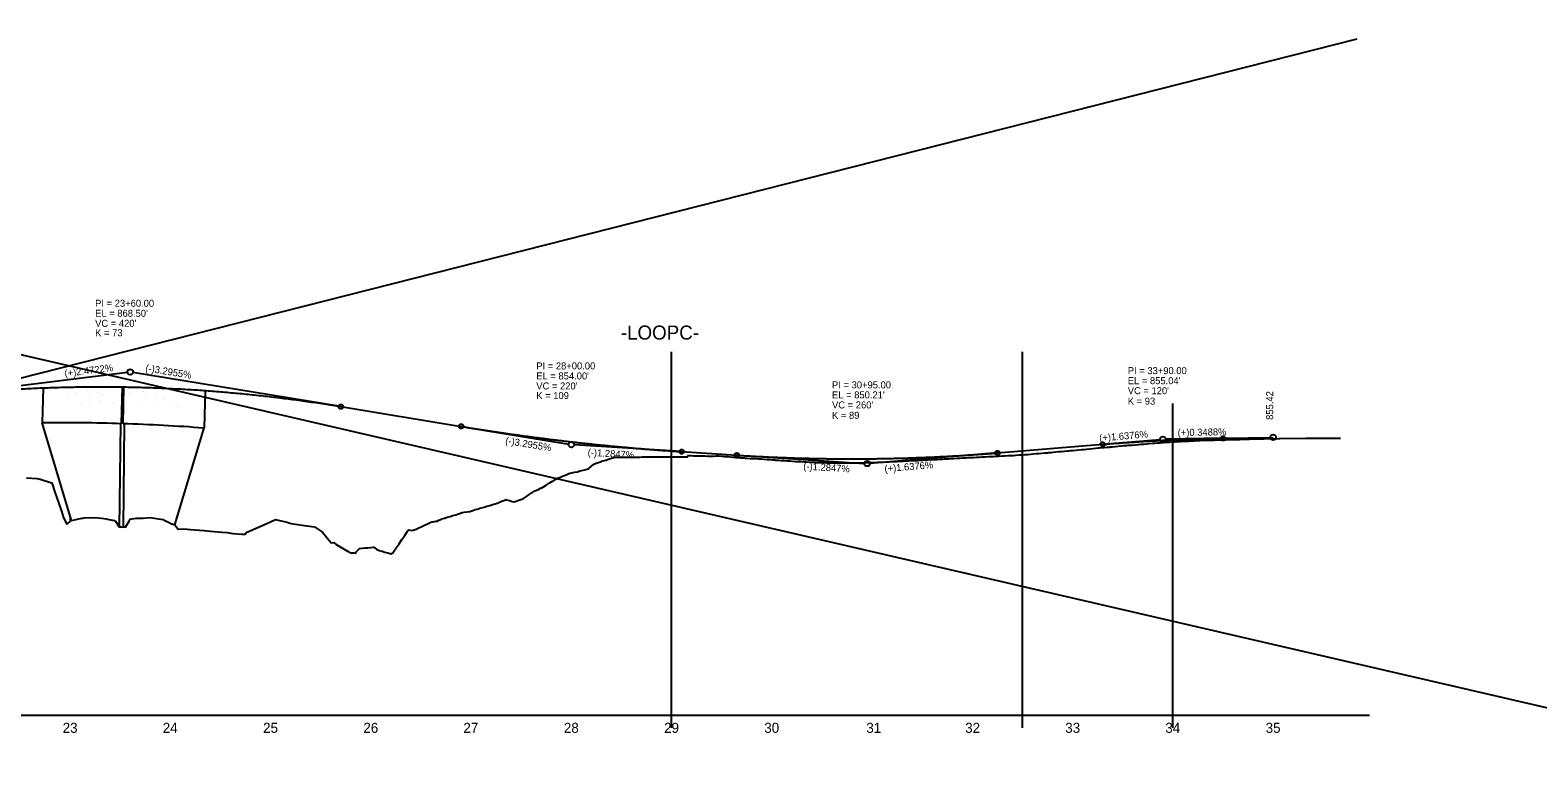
# Model space of a CAD drawing. Extents: x 570622 to 580296, y -55533 to -48575.
# Drawn here: x 575281 to 576785, y -51546 to -50801 of the extents above; entities that cross this region are included whole.
import ezdxf

# ---------------------------------------------------------------- set-up
doc = ezdxf.new("R2010")
doc.units = 0
for name, color, linetype in [('Default', 7, 'Continuous'), ('Exist Profile Cell', 7, 'Continuous'), ('Exist Vertical Profile Ground Line', 7, 'Continuous'), ('Exist Vertical Profile Horizontal Axis Label Major', 7, 'Continuous'), ('Prop Vertical Profile Curve Label', 7, 'Continuous'), ('Prop Vertical Profile Grade', 7, 'Continuous'), ('Prop Vertical Profile Grade Label', 7, 'Continuous'), ('Prop VPI Label', 7, 'Continuous')]:
    doc.layers.add(name, color=color, linetype=linetype)

msp = doc.modelspace()

# ---------------------------------------------------------------- linework, layer by layer
at = {"layer": 'Default'}
for p, q in [((575921, -51497.2), (575921, -51122)), ((576271, -51497.2), (576271, -51122)), ((575294.2, -51158.1), (575293, -51192.8)), ((575372.4, -51193.7), (575373.3, -51157.2)), ((575373.8, -51193.8), (575374.7, -51157.2)), ((575318.1, -51164.1), (575318.1, -51164.1)), ((575319.5, -51165.7), (575319.5, -51165.7)), ((575319.5, -51165.7), (575319.5, -51165.7)), ((575326.2, -51162.4), (575326.2, -51162.4)), ((575327.7, -51164), (575327.7, -51164)), ((575327.7, -51164), (575327.7, -51164)), ((575331.3, -51174.5), (575331.3, -51174.5)), ((575331.3, -51174.5), (575331.3, -51174.5)), ((575337.9, -51162.1), (575337.9, -51162.1)), ((575339.4, -51163.7), (575339.4, -51163.7)), ((575339.5, -51163.7), (575339.5, -51163.7)), ((575339.7, -51172.3), (575339.7, -51172.3)), ((575339.7, -51172.3), (575339.7, -51172.3)), ((575349.6, -51163.2), (575349.6, -51163.2)), ((575351.1, -51164.8), (575351.1, -51164.8)), ((575351.1, -51164.8), (575351.1, -51164.8)), ((575351.3, -51171.9), (575351.3, -51171.9)), ((575351.5, -51171.9), (575351.5, -51171.9)), ((575352.3, -51164), (575352.3, -51164)), ((575353.8, -51165.6), (575353.8, -51165.6)), ((575353.8, -51165.6), (575353.8, -51165.6)), ((575363, -51173), (575363, -51173)), ((575363, -51173), (575363, -51173)), ((575365.7, -51173.7), (575365.7, -51173.7)), ((575365.7, -51173.7), (575365.7, -51173.7)), ((575380, -51162.5), (575380, -51162.5)), ((575381.5, -51164.1), (575381.5, -51164.1)), ((575381.5, -51164.1), (575381.5, -51164.1)), ((575393.3, -51161.8), (575393.3, -51161.8)), ((575393.3, -51172.6), (575393.3, -51172.6)), ((575393.3, -51172.6), (575393.3, -51172.6)), ((575394.1, -51162.2), (575394.1, -51162.2)), ((575395.1, -51163.4), (575395.1, -51163.4)), ((575406.6, -51163.8), (575406.6, -51163.8)), ((575406.7, -51171.9), (575406.7, -51171.9)), ((575407, -51171.9), (575407, -51171.9)), ((575408.1, -51165.5), (575408.1, -51165.5)), ((575408.1, -51165.5), (575408.1, -51165.5)), ((575414.3, -51168.3), (575414.3, -51168.3)), ((575416.3, -51169.9), (575416.3, -51169.9)), ((575416.3, -51169.9), (575416.3, -51169.9)), ((575420, -51173.8), (575420, -51173.8)), ((575420, -51173.8), (575420, -51173.8)), ((575455.8, -51160.8), (575454.6, -51198.1)), ((576421, -51497.2), (576421, -51173.7)), ((575428.5, -51178), (575428.5, -51178)), ((575428.5, -51178), (575428.5, -51178)), ((575322.3, -51290.3), (575293, -51192.8)), ((575370.4, -51297.3), (575371.5, -51193.8)), ((575374.2, -51297.4), (575375.3, -51193.8)), ((575425.6, -51294.6), (575454.6, -51198.1)), ((576268.6, -51221), (576268.6, -51221)), ((575321.3, -51290.3), (575321.3, -51287)), ((575322.3, -51290.3), (575321.3, -51290.3))]:
    msp.add_line(p, q, dxfattribs=at)
for start, end in [(88.1608, 90.5075), (85.7299, 88.1202)]:
    msp.add_arc((575310.2, -53131.3), 1938.5, start, end, dxfattribs=at)
at = {"layer": 'Exist Profile Cell'}
for p, q in [((576604.4, -50810.1), (573705.9, -51546.1)), ((573874.3, -50801.3), (576976.7, -51519.5)), ((574021, -51484.7), (576617.2, -51484.7))]:
    msp.add_line(p, q, dxfattribs=at)
at = {"layer": 'Exist Vertical Profile Ground Line'}
for points in [[(576264.1, -51225.3), (576264.7, -51225.2), (576267.6, -51225), (576270.4, -51224.9), (576273.2, -51224.7), (576276.2, -51224.5), (576278.8, -51224.2), (576281.7, -51224), (576284.5, -51223.7), (576287.3, -51223.5), (576290.1, -51223.3), (576293, -51223), (576295.8, -51222.8), (576296.7, -51222.7), (576298.6, -51222.5), (576299.5, -51222.4), (576301.4, -51222.3), (576304.3, -51222), (576307.1, -51221.7), (576309.9, -51221.4), (576312.7, -51221.2), (576315.6, -51220.9), (576316.7, -51220.8), (576318.4, -51220.7), (576320, -51220.6), (576321.2, -51220.5), (576324, -51220.2), (576326.9, -51219.9), (576329.7, -51219.7), (576332.5, -51219.4), (576334.7, -51219.2), (576335.3, -51219.1), (576338.1, -51218.8), (576341, -51218.5), (576343.8, -51218.3), (576346.6, -51218), (576347.4, -51217.9), (576349.4, -51217.7), (576352.3, -51217.5), (576355.1, -51217.3), (576357.9, -51217.1), (576358.5, -51217), (576360.7, -51216.8), (576363.6, -51216.5), (576366.4, -51216.3), (576369.2, -51216), (576369.7, -51215.9), (576372, -51215.7), (576374.9, -51215.5), (576376.4, -51215.4), (576377.7, -51215.3), (576379.1, -51215.2), (576380.5, -51215.1), (576383.3, -51214.8), (576386.2, -51214.6), (576386.9, -51214.6), (576389, -51214.4), (576391.8, -51214.2), (576394.6, -51213.9), (576397.4, -51213.7), (576400.5, -51213.4), (576403.1, -51213.2), (576405.9, -51213), (576408.7, -51212.8), (576411.6, -51212.6), (576414.4, -51212.4), (576417.2, -51212.2), (576417.7, -51212.1), (576420, -51212), (576421.1, -51211.9), (576422.9, -51211.8), (576425.7, -51211.7), (576428.5, -51211.5), (576431.3, -51211.4), (576434.2, -51211.2), (576437, -51211.1), (576439.8, -51210.9), (576442.6, -51210.8), (576444.9, -51210.7), (576445.5, -51210.6), (576448.3, -51210.5), (576450.4, -51210.4), (576451.1, -51210.3), (576454.1, -51210.3), (576456.7, -51210.2), (576459.6, -51210.1), (576462.4, -51210.1), (576465.2, -51210), (576468, -51209.9), (576470.9, -51209.9), (576472.2, -51209.8), (576473.7, -51209.8), (576476.5, -51209.7), (576479.3, -51209.7), (576482.2, -51209.6), (576485, -51209.5), (576487.8, -51209.5), (576490.6, -51209.4), (576493.5, -51209.3), (576495.9, -51209.3), (576496.3, -51209.3)], [(576496.3, -51209.3), (576496.8, -51209.3), (576497.4, -51209.2), (576526.8, -51208.7), (576527.5, -51208.6), (576553.5, -51208.1), (576554.5, -51208.1), (576583.6, -51208.4), (576588, -51208.4)], [(575810.1, -51247), (575812.9, -51245.9), (575815.7, -51244.7), (575818.6, -51243.6), (575819.3, -51243.2), (575821.4, -51242.9), (575824.2, -51242.3), (575827, -51241.7), (575829.9, -51241), (575832.7, -51240.3), (575835.5, -51239.6), (575837.6, -51239), (575838.3, -51238.4), (575841.2, -51236.1), (575843.3, -51234.3), (575844, -51234), (575846.8, -51233), (575849, -51232.2), (575849.6, -51232), (575852.5, -51231), (575854, -51230.5), (575855.3, -51230.1), (575858.1, -51229.2), (575860.9, -51228.3), (575863.7, -51227.4), (575864.3, -51227.3), (575866.6, -51227.2), (575869.4, -51227.2), (575872.2, -51227.1), (575874.3, -51227.1), (575875, -51227.1), (575877.9, -51227.2), (575878.3, -51227.2), (575880.7, -51227.1), (575883.5, -51227.1), (575886.3, -51227.1), (575889.2, -51227.1), (575892, -51227), (575894.8, -51227), (575897.6, -51227), (575900.5, -51226.9), (575903.3, -51226.9), (575904.2, -51226.9), (575906.1, -51226.9), (575908.9, -51226.9), (575911.8, -51226.9), (575914.6, -51227), (575916.7, -51227), (575917.4, -51227), (575920.2, -51227), (575923, -51227), (575925.9, -51227), (575927.2, -51227), (575928.7, -51227), (575931.5, -51227), (575934.3, -51227), (575936.8, -51227), (575937.2, -51225.6), (575940, -51225.7), (575942.8, -51225.8), (575945.6, -51225.8), (575948.5, -51225.9), (575951.3, -51226), (575954.1, -51226), (575956.9, -51226.1), (575959.8, -51226.1), (575960.9, -51226.2), (575961.4, -51226.1), (575962.6, -51226.2), (575965.4, -51226), (575967.1, -51225.8), (575968.2, -51225.9), (575971.1, -51226.2), (575973.4, -51226.4), (575973.9, -51226.5), (575976.7, -51226.7), (575979.5, -51226.9), (575982.3, -51227.1), (575985.2, -51227.4), (575988, -51227.6), (575990.1, -51227.8), (575990.8, -51227.8), (575993.6, -51228), (575994.1, -51228.1), (575996.5, -51228.2), (575999.3, -51228.4), (576002.1, -51228.5), (576004.9, -51228.7), (576007.8, -51228.9), (576010.6, -51229), (576012.9, -51229.2), (576013.4, -51229.2), (576016.2, -51229.4), (576019.1, -51229.6), (576021.9, -51229.8), (576023.8, -51230), (576024.7, -51230.1), (576027.5, -51230.2), (576030.4, -51230.4), (576032.4, -51230.6), (576033.2, -51230.6)], [(576033.2, -51230.6), (576036, -51230.8), (576038.8, -51231), (576041.6, -51231.2), (576044.5, -51231.4), (576047.6, -51231.6), (576050.1, -51231.7), (576052.9, -51231.8), (576055.8, -51232), (576058.6, -51232.1), (576060.8, -51232.3), (576061.4, -51232.3), (576062.1, -51232.3), (576062.4, -51232.3), (576064.2, -51232.4), (576067.1, -51232.5), (576069.9, -51232.5), (576072.7, -51232.6), (576075.5, -51232.7), (576078.4, -51232.8), (576081.2, -51232.9), (576082.6, -51232.9), (576084, -51232.9), (576086.9, -51232.9), (576089.7, -51232.9), (576092.5, -51232.9), (576095.3, -51232.9), (576098.1, -51232.9), (576100.9, -51232.9), (576103, -51232.9), (576103.8, -51232.9), (576106.6, -51232.8), (576109.4, -51232.7), (576110.2, -51232.7), (576112.2, -51232.7), (576115.1, -51232.6), (576117.9, -51232.5), (576119, -51232.5), (576120.7, -51232.4), (576123.5, -51232.4), (576126.4, -51232.3), (576129.2, -51232.2), (576130.1, -51232.2), (576132, -51232.1), (576134.8, -51231.9), (576137.7, -51231.8), (576140.5, -51231.6), (576142.3, -51231.5), (576143.3, -51231.5), (576146.1, -51231.4), (576149, -51231.2), (576151.8, -51231.1), (576154.6, -51231), (576157.4, -51230.8), (576160.2, -51230.7), (576163.1, -51230.5), (576165.9, -51230.4), (576166.7, -51230.3), (576168.7, -51230.2), (576171.5, -51230.1), (576174.4, -51230), (576176.6, -51229.9), (576177.2, -51229.8), (576180, -51229.7), (576182.8, -51229.5), (576185.7, -51229.4), (576188.5, -51229.2), (576191.3, -51229.1), (576192.5, -51229), (576194.1, -51228.9), (576196.2, -51228.8), (576197, -51228.8), (576199.8, -51228.6), (576202.6, -51228.4), (576205.4, -51228.3), (576208.3, -51228.1), (576211.1, -51227.9), (576213.9, -51227.8), (576214.4, -51227.8), (576216.7, -51227.6), (576217.3, -51227.6), (576219.5, -51227.5), (576220.3, -51227.5), (576222.4, -51227.4), (576225.2, -51227.2), (576228, -51227.1), (576230.8, -51226.9), (576233.7, -51226.8), (576236.5, -51226.7), (576238.2, -51226.6), (576239.3, -51226.5), (576242.1, -51226.4), (576245, -51226.2), (576247.8, -51226.1), (576250.6, -51226), (576253.4, -51225.8), (576256.3, -51225.7), (576259.1, -51225.5), (576260.3, -51225.5), (576261.9, -51225.4), (576264.1, -51225.3)], [(575277.6, -51247.7), (575287.9, -51248.6), (575291, -51249.1), (575301.4, -51252.4), (575302.7, -51252.7), (575303.6, -51254.8), (575305.4, -51261), (575312.5, -51281.1), (575314.4, -51287.7), (575317.8, -51294.2), (575322.3, -51290.3), (575325.4, -51289.8), (575332.7, -51288.1), (575333.7, -51287.9), (575335.5, -51287.8), (575345.5, -51287.5), (575352.2, -51288.1), (575357.1, -51288.6), (575358.2, -51288.9), (575359.8, -51289.4), (575365.2, -51290.5), (575366.1, -51290.8), (575366.4, -51291.2), (575370, -51296.7), (575372.5, -51296.8), (575376.4, -51296.9), (575379.8, -51291.2), (575381, -51289.1), (575382.5, -51288.8), (575387.3, -51288.2), (575394, -51287.9), (575401, -51287.5), (575413.4, -51289.4), (575414.1, -51289.5), (575414.8, -51289.9), (575419.7, -51292.3), (575422.3, -51293.6), (575422.9, -51293.8), (575425.6, -51294.6), (575428.3, -51298.7), (575429.5, -51299.1), (575434.4, -51298.8), (575441.2, -51299.3), (575454.7, -51300.2), (575461, -51301), (575472.5, -51301.9), (575477.6, -51302.5), (575483.3, -51303.4), (575492.3, -51303.9), (575495.7, -51304), (575497.1, -51301.9), (575498.3, -51301.7), (575520.1, -51292.2), (575526, -51289.4), (575528.7, -51290.2), (575537.6, -51291.9), (575540.3, -51293.2), (575541.6, -51293.5), (575543.4, -51293.8), (575557.3, -51295.8), (575564.8, -51296.7)], [(575564.8, -51296.7), (575572.9, -51301.9), (575581.3, -51312.5), (575584.1, -51312.2), (575586.5, -51314.4), (575598.3, -51321.4), (575600.4, -51322.7), (575601.1, -51322.7), (575604, -51322.8), (575605.3, -51322.9), (575606.8, -51321.2), (575609.6, -51318.2), (575612.4, -51318), (575615.3, -51317.8), (575618.1, -51317.6), (575620.9, -51317.4), (575623.7, -51317.1), (575624.1, -51317.1), (575626.5, -51318.9), (575627.8, -51319.8), (575629.4, -51320.2), (575632.2, -51321.1), (575635, -51321.9), (575637.8, -51322.7), (575640.9, -51323.5), (575642.8, -51322.7), (575643.5, -51321.7), (575646.3, -51317.7), (575649.1, -51313.6), (575652, -51309.4), (575654.8, -51305.3), (575657.6, -51301.1), (575658.6, -51299.7), (575660.4, -51299.9), (575662.9, -51300.2), (575663.3, -51300.1), (575666.1, -51298.9), (575668.9, -51297.6), (575671.7, -51296.4), (575674.6, -51295.1), (575677.4, -51293.8), (575680.2, -51292.5), (575681.7, -51291.8), (575683, -51291.6), (575685.8, -51291.1), (575687.2, -51290.9), (575688.7, -51290.2), (575691.5, -51288.9), (575691.9, -51288.6), (575694.3, -51288), (575697.1, -51287.2), (575700, -51286.3), (575702.8, -51285.5), (575705.6, -51284.6), (575708.4, -51283.7), (575711.3, -51282.7), (575712.2, -51282.4), (575714.1, -51282.2), (575716.9, -51281.9), (575719.7, -51281.5), (575722.6, -51280.4), (575725, -51279.5), (575725.4, -51279.4), (575728.2, -51278.6), (575729.6, -51278.2), (575731, -51277.8), (575733.9, -51277), (575736.7, -51276.2), (575739.5, -51275.3), (575742.3, -51274.5), (575745.1, -51273.6), (575748, -51272.7), (575749.2, -51272.2), (575750.8, -51271.6), (575753.6, -51270.5), (575755.9, -51269.5), (575756.4, -51269.7), (575759.3, -51270.5), (575762.1, -51271.3), (575764, -51271.8), (575764.9, -51271.5), (575767.7, -51270.5), (575770.6, -51269.5), (575773.4, -51268.4), (575776.2, -51266.4), (575779, -51264.4), (575781.9, -51262.4), (575782.4, -51262), (575784.7, -51260.9), (575787.5, -51259.7), (575790.3, -51258.3), (575791.4, -51257.8), (575793.2, -51256.8), (575796, -51255), (575798.8, -51253.3), (575801.6, -51251.5), (575804.4, -51249.7), (575805.6, -51249), (575807, -51248.2), (575807.3, -51248.1), (575810.1, -51247)]]:
    msp.add_lwpolyline(points, dxfattribs=at)
at = {"layer": 'Prop Vertical Profile Curve Label'}
for centre in [(575591, -51176.8), (575711, -51196.5), (575931, -51221.7), (576351, -51214.4), (576471, -51208.4), (575986, -51225.3), (576246, -51223)]:
    msp.add_circle(centre, 2.25, dxfattribs=at)
at = {"layer": 'Prop Vertical Profile Grade'}
for p, q in [((575591, -51176.8), (575711, -51196.5)), ((576246, -51223), (576351, -51214.4)), ((576471, -51208.4), (576521, -51207.5)), ((575931, -51221.7), (575986, -51225.3))]:
    msp.add_line(p, q, dxfattribs=at)
for points in [[(575171, -51168.1), (575179.4, -51167.1), (575187.8, -51166.1), (575196.2, -51165.2), (575204.6, -51164.3), (575213, -51163.5), (575221.4, -51162.8), (575229.8, -51162), (575238.2, -51161.4), (575246.6, -51160.7), (575255, -51160.2), (575263.4, -51159.6), (575271.8, -51159.1), (575280.2, -51158.7), (575288.6, -51158.3), (575297, -51158), (575305.4, -51157.7), (575313.8, -51157.5), (575322.2, -51157.3), (575330.6, -51157.1), (575339, -51157), (575347.4, -51157), (575355.8, -51157), (575364.2, -51157), (575372.6, -51157.1), (575381, -51157.3), (575389.4, -51157.5), (575397.8, -51157.7), (575406.2, -51158), (575414.6, -51158.4), (575423, -51158.8), (575431.4, -51159.2), (575439.8, -51159.7), (575448.2, -51160.2), (575456.6, -51160.8), (575465, -51161.4), (575473.4, -51162.1), (575481.8, -51162.9), (575490.2, -51163.6), (575498.6, -51164.5), (575507, -51165.3), (575515.4, -51166.3), (575523.8, -51167.2), (575532.2, -51168.3), (575540.6, -51169.3), (575549, -51170.4), (575557.4, -51171.6), (575565.8, -51172.8), (575574.2, -51174.1), (575582.6, -51175.4), (575591, -51176.8)], [(575711, -51196.5), (575715.4, -51197.2), (575719.8, -51198), (575724.2, -51198.7), (575728.6, -51199.4), (575733, -51200), (575737.4, -51200.7), (575741.8, -51201.4), (575746.2, -51202), (575750.6, -51202.7), (575755, -51203.3), (575759.4, -51204), (575763.8, -51204.6), (575768.2, -51205.2), (575772.6, -51205.8), (575777, -51206.4), (575781.4, -51207), (575785.8, -51207.6), (575790.2, -51208.1), (575794.6, -51208.7), (575799, -51209.3), (575803.4, -51209.8), (575807.8, -51210.3), (575812.2, -51210.9), (575816.6, -51211.4), (575821, -51211.9), (575825.4, -51212.4), (575829.8, -51212.9), (575834.2, -51213.4), (575838.6, -51213.8), (575843, -51214.3), (575847.4, -51214.8), (575851.8, -51215.2), (575856.2, -51215.6), (575860.6, -51216.1), (575865, -51216.5), (575869.4, -51216.9), (575873.8, -51217.3), (575878.2, -51217.7), (575882.6, -51218.1), (575887, -51218.5), (575891.4, -51218.8), (575895.8, -51219.2), (575900.2, -51219.5), (575904.6, -51219.9), (575909, -51220.2), (575913.4, -51220.5), (575917.8, -51220.8), (575922.2, -51221.1), (575926.6, -51221.4), (575931, -51221.7)], [(576351, -51214.4), (576353.4, -51214.2), (576355.8, -51214), (576358.2, -51213.8), (576360.6, -51213.6), (576363, -51213.4), (576365.4, -51213.2), (576367.8, -51213.1), (576370.2, -51212.9), (576372.6, -51212.7), (576375, -51212.6), (576377.4, -51212.4), (576379.8, -51212.2), (576382.2, -51212.1), (576384.6, -51211.9), (576387, -51211.8), (576389.4, -51211.6), (576391.8, -51211.5), (576394.2, -51211.3), (576396.6, -51211.2), (576399, -51211), (576401.4, -51210.9), (576403.8, -51210.8), (576406.2, -51210.7), (576408.6, -51210.5), (576411, -51210.4), (576413.4, -51210.3), (576415.8, -51210.2), (576418.2, -51210.1), (576420.6, -51210), (576423, -51209.9), (576425.4, -51209.8), (576427.8, -51209.7), (576430.2, -51209.6), (576432.6, -51209.5), (576435, -51209.4), (576437.4, -51209.3), (576439.8, -51209.2), (576442.2, -51209.1), (576444.6, -51209), (576447, -51209), (576449.4, -51208.9), (576451.8, -51208.8), (576454.2, -51208.8), (576456.6, -51208.7), (576459, -51208.6), (576461.4, -51208.6), (576463.8, -51208.5), (576466.2, -51208.5), (576468.6, -51208.4), (576471, -51208.4)], [(575986, -51225.3), (575991.2, -51225.6), (575996.4, -51225.9), (576001.6, -51226.2), (576006.8, -51226.5), (576012, -51226.7), (576017.2, -51227), (576022.4, -51227.2), (576027.6, -51227.4), (576032.8, -51227.6), (576038, -51227.8), (576043.2, -51228), (576048.4, -51228.2), (576053.6, -51228.3), (576058.8, -51228.4), (576064, -51228.6), (576069.2, -51228.7), (576074.4, -51228.7), (576079.6, -51228.8), (576084.8, -51228.9), (576090, -51228.9), (576095.2, -51228.9), (576100.4, -51228.9), (576105.6, -51228.9), (576110.8, -51228.9), (576116, -51228.9), (576121.2, -51228.8), (576126.4, -51228.7), (576131.6, -51228.6), (576136.8, -51228.5), (576142, -51228.4), (576147.2, -51228.3), (576152.4, -51228.2), (576157.6, -51228), (576162.8, -51227.8), (576168, -51227.6), (576173.2, -51227.4), (576178.4, -51227.2), (576183.6, -51227), (576188.8, -51226.7), (576194, -51226.5), (576199.2, -51226.2), (576204.4, -51225.9), (576209.6, -51225.6), (576214.8, -51225.2), (576220, -51224.9), (576225.2, -51224.5), (576230.4, -51224.2), (576235.6, -51223.8), (576240.8, -51223.4), (576246, -51223)]]:
    msp.add_spline(points, degree=3, dxfattribs=at)
at = {"layer": 'Prop VPI Label'}
for p, q in [((575171, -51168.1), (575378.3, -51142.5)), ((575591, -51176.8), (575383.7, -51142.6)), ((575711, -51196.5), (575818.3, -51214.2)), ((575931, -51221.7), (575823.7, -51214.8)), ((576351, -51214.4), (576408.3, -51209.7)), ((576471, -51208.4), (576413.7, -51209.4)), ((575986, -51225.3), (576113.3, -51233.4)), ((576246, -51223), (576118.7, -51233.4))]:
    msp.add_line(p, q, dxfattribs=at)
for centre in [(575381, -51142.2), (576521, -51207.5), (575821, -51214.7), (576411, -51209.4), (576116, -51233.6)]:
    msp.add_circle(centre, 2.75, dxfattribs=at)

# ---------------------------------------------------------------- texts
at = {"layer": 'Exist Profile Cell'}
msp.add_text('-LOOPC-', height=14, dxfattribs=at).set_placement((575870.3, -51109.9))
at = {"layer": 'Exist Vertical Profile Horizontal Axis Label Major'}
for s, p in [('23', (575313.6, -51502.2)), ('24', (575413.4, -51502.2)), ('25', (575513.5, -51502.2)), ('26', (575613.5, -51502.2)), ('27', (575713.3, -51502.2)), ('28', (575813.5, -51502.2)), ('29', (575913.5, -51502.2)), ('30', (576013.4, -51502.2)), ('31', (576115.2, -51502.2)), ('32', (576213.8, -51502.2)), ('33', (576313.6, -51502.2)), ('34', (576413.4, -51502.2)), ('35', (576513.5, -51502.2))]:
    msp.add_text(s, height=10, dxfattribs=at).set_placement(p)
at = {"layer": 'Prop Vertical Profile Curve Label'}
for s, p in [("VC = 420'", (575346, -51097.2)), ('K = 73', (575346, -51106.6)), ("VC = 220'", (575786, -51159.7)), ("VC = 120'", (576376, -51164.4)), ('K = 109', (575786, -51169.3)), ("VC = 260'", (576081, -51178.6)), ('K = 93', (576376, -51174.8)), ('K = 89', (576081, -51189))]:
    msp.add_text(s, height=7, dxfattribs=at).set_placement(p)
at = {"layer": 'Prop Vertical Profile Grade Label'}
for s, rotation, p in [('(+)2.4722%', 7.0466, (575315.9, -51147.2)), ('(-)3.2955%', 350.6433, (575395.7, -51141.5)), ('(+)1.6376%', 4.681, (576347.8, -51211.6)), ('(+)0.3488%', 0.9992, (576425.8, -51206.2)), ('(-)3.2955%', 350.6433, (575754.7, -51213.9)), ('(-)1.2847%', 356.3245, (575837.1, -51225.7)), ('(-)1.2847%', 356.3245, (576052.2, -51239.5)), ('(+)1.6376%', 4.681, (576133.6, -51242.2))]:
    msp.add_text(s, height=7, rotation=rotation, dxfattribs=at).set_placement(p)
at = {"layer": 'Prop VPI Label'}
for s, p in [('PI = 23+60.00', (575346, -51077.2)), ("EL = 868.50'", (575346, -51087.2)), ('PI = 28+00.00', (575786, -51139.7)), ("EL = 854.00'", (575786, -51149.7)), ('PI = 33+90.00', (576376, -51144.4)), ('PI = 30+95.00', (576081, -51158.6)), ("EL = 855.04'", (576376, -51154.4)), ("EL = 850.21'", (576081, -51168.6))]:
    msp.add_text(s, height=7, dxfattribs=at).set_placement(p)
msp.add_text('855.42', height=7, rotation=90, dxfattribs=at).set_placement((576521, -51190))

doc.saveas('drawing.dxf')
